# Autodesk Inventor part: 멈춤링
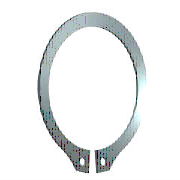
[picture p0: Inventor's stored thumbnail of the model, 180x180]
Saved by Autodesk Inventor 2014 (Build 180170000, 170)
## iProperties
Created: 2014-12
Part Number: 멈춤링
Material: 강, 연강
Description: 리테이닝 링(C형)
Document SubType Name: Modeling
Standard: KS B 1336
Designer: KYOUNG IL JANG
Standards Organization: KS
Language: ko-KR
Size Designation: 17 x 1
Categories: <MemberInstance><Categories><Category DisplayName="샤프트 부품" InternalName="7f7aeb1f-a693-4053-b835-cee3144e0d98" Mnemonic="SHFT"><Category DisplayName="써클립" Inter
Density: 7.86 g/cm^3
Mass: 0.979804 g
Surface Area: 3.83537 cm^2
Volume: 0.124657 cm^3
Appearance: 진녹색
Company: 한국ATC센터
Author: KYOUNG IL JANG
IsCustomPart: 0
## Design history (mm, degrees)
sketch "스케치1"
  geometry: L1 (-6, 0)-(6, 0) reference; L2 (0, 20.189)-(0, -80.536) reference; L3 (-48.09, 0)-(48.09, 0) reference; L4 (-0.425, -16.589)-(-0.425, -20.289); L5 (-0.425, -6.54)-(-0.425, -13.29); L6 (-2.795, 2.2)-(3.672, 2.2); L7 (0.425, -6.54)-(0.425, -13.29); L8 (0.425, -16.589)-(0.425, -20.289); C1 r 0.85 at (-1.7, -18.452); C2 r 0.85 at (1.7, -18.452); A1 r 8.1 centre (0, -8.5) between (0.425, -16.589) and (-0.425, -16.589); A2 r 10.15 centre (0, -7.95) between (4.363, -17.114) and (-4.363, -17.114); A3 r 11.797 centre (0, -8.5) between (-1.986, -20.128) and (-0.425, -20.289); A4 r 1.7 centre (-1.7, -18.452) between (-3.397, -18.551) and (-1.986, -20.128); A5 r 1.7 centre (-5.094, -18.649) between (-3.397, -18.551) and (-4.363, -17.114); A6 r 1.7 centre (5.094, -18.649) between (4.363, -17.114) and (3.397, -18.551); A7 r 1.7 centre (1.7, -18.452) between (1.986, -20.128) and (3.397, -18.551); A8 r 11.797 centre (0, -8.5) between (0.425, -20.289) and (1.986, -20.128)
  constraints: 16 point on circle, 12 end point, 10 centre point, 9 symmetric about line, 5 point on line, 4 tangent, 3 coincident, 2 horizontal, 1 perpendicular, 1 vertical, 5 other
  dimensions: "d0" = 16.2 diameter of A1 (= ND); "d1" = 3.7 distance of L4.end L4.start (= SRB2); "d6" = 0.425 distance between parallel lines of L2 L5 (= 0.25 x SD5); "d7" = 2.2 distance between parallel lines of L6 L3 (= SRB1); "d8" = 0.55 distance of A1.centre A2.centre (= 0.25 x SRB1); "d9" = 1.7 radius of A4 (= SD5); "d10" = 1.7 radius of A5 (= SD5); "d11" = 1.275 distance from line of L4 A4.centre (= 0.75 x SD5); "d12" = 1.7 diameter of C1 (= SD5); "d13" = 1.7 diameter of C2 (= SD5); "d14" = 8.5 distance from line of A1.centre L1 (= 0.5 x WD)
extrude "본체" new body sketch "스케치1" distance "d2" = 1 (= SD); taper "d3" = 0 deg
workaxis "Work Axis1"
workplane "Work Plane1"
body "Solid1"
other parameters: "WD" = 17 (= WDMIN) [user parameter; used in 1 equation term], "SD" = 1 [user parameter; used in 1 equation term], "SRB1" = 2.2 [user parameter; used in 2 equation terms], "ND" = 16.2 [user parameter; used in 1 equation term], "SRB2" = 3.7 [user parameter; used in 1 equation term], "SD5" = 1.7 [user parameter; used in 6 equation terms], "d15" = 0, "d16" = 0, "d17" = 0, "d41" = 0, "d42" = 0, "WDMIN" = 17 [user parameter; used in 1 equation term], "SD3" = 15.7 [user parameter], "WDMAX" = 18 [user parameter]
